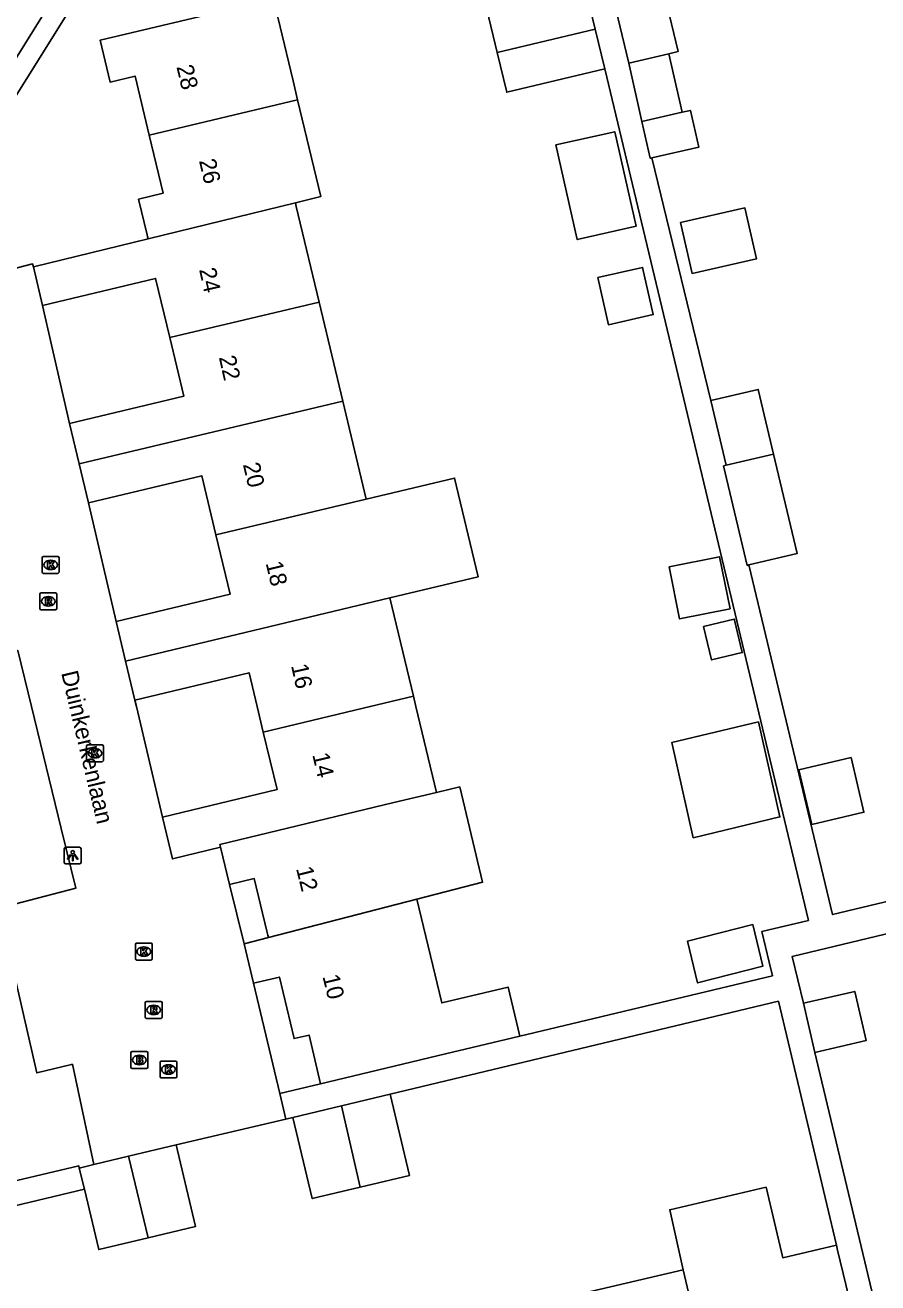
# Model space of a CAD drawing. Extents: x 158474 to 159560, y 388525 to 389605.
# Drawn here: x 159385.3 to 159435.9, y 388715.8 to 388790.4 of the extents above; entities that cross this region are included whole.
import ezdxf

# ---------------------------------------------------------------- set-up
doc = ezdxf.new("R2010")
doc.units = 0
for name, color, linetype in [('IMGEO_Brandkraan', 7, 'Continuous'), ('IMGEO_Kolk', 7, 'Continuous'), ('IMGEO_Lichtpunt', 7, 'Continuous'), ('IMGEO_Muur', 7, 'Continuous'), ('IMGEO_Openbare_ruimte_label', 7, 'Continuous'), ('IMGEO_Pand', 7, 'Continuous'), ('IMGEO_Pand_nummerreeks', 7, 'Continuous'), ('IMGEO_Rijbaan_lokaal_open', 7, 'Continuous'), ('IMGEO_Rioolput', 7, 'Continuous'), ('IMGEO_Voetpad_open', 7, 'Continuous')]:
    doc.layers.add(name, color=color, linetype=linetype)

msp = doc.modelspace()

# ---------------------------------------------------------------- linework, layer by layer
at = {"layer": 'IMGEO_Brandkraan'}
for p, q in [((159391.554, 388728.601), (159391.554, 388729.453)), ((159391.629, 388729.527), (159392.481, 388729.527)), ((159392.555, 388729.453), (159392.555, 388728.601)), ((159392.065, 388728.747), (159392.04, 388728.747)), ((159392.042, 388729.307), (159392.067, 388729.307)), ((159392.481, 388728.527), (159391.629, 388728.527))]:
    msp.add_line(p, q, dxfattribs=at)
for points in [[(159391.554, 388728.601), (159391.554, 388729.453)], [(159391.629, 388729.527), (159392.481, 388729.527)], [(159392.555, 388729.453), (159392.555, 388728.601)], [(159391.902, 388729.227), (159391.902, 388728.827), (159392.115, 388728.827)], [(159392.133, 388729.227), (159391.902, 388729.227)], [(159392.081, 388729.146), (159392.027, 388729.146), (159392.027, 388729.07)], [(159392.027, 388729.07), (159392.08, 388729.07)], [(159392.089, 388728.994), (159392.027, 388728.994), (159392.027, 388728.913)], [(159392.027, 388728.913), (159392.089, 388728.913)], [(159392.481, 388728.527), (159391.629, 388728.527)]]:
    msp.add_lwpolyline(points, dxfattribs=at)
for centre, radius, start, end in [((159391.631, 388729.451), 0.0765, 91.55205, 178.44795), ((159391.631, 388729.451), 0.0765, 91.55205, 178.44795), ((159392.479, 388729.451), 0.0765, 1.55205, 88.44795), ((159392.479, 388729.451), 0.0765, 1.55205, 88.44795), ((159392.082, 388729.108), 0.0379, 267.82845, 90.93552), ((159392.09, 388728.953), 0.0404, 269.87594, 90.50774), ((159392.121, 388729.078), 0.251, 268.66757, 293.53466), ((159392.137, 388729.082), 0.145, 59.4692, 91.53667), ((159392.162, 388729.129), 0.0922, 285.51372, 58.15012), ((159392.167, 388728.937), 0.105, 301.31148, 78.98903), ((159391.631, 388728.603), 0.0765, 181.55205, 268.44795), ((159391.631, 388728.603), 0.0765, 181.55205, 268.44795), ((159392.479, 388728.603), 0.0765, 271.55205, 358.44795), ((159392.479, 388728.603), 0.0765, 271.55205, 358.44795)]:
    msp.add_arc(centre, radius, start, end, dxfattribs=at)
for centre, major_axis, ratio, start_param, end_param in [((159392.041, 388729.027), (-0.387, 0.002), 0.722429, 4.712389, 7.853982), ((159392.066, 388729.027), (-0.39, 0.002), 0.717154, 1.570796, 4.712389)]:
    msp.add_ellipse(centre, major_axis=major_axis, ratio=ratio, start_param=start_param, end_param=end_param, dxfattribs=at)
at = {"layer": 'IMGEO_Kolk'}
for p, q in [((159386.289, 388757.982), (159386.289, 388758.834)), ((159386.364, 388758.908), (159387.216, 388758.908)), ((159386.777, 388758.688), (159386.802, 388758.688)), ((159387.29, 388758.834), (159387.29, 388757.982)), ((159387.216, 388757.908), (159386.364, 388757.908)), ((159386.8, 388758.128), (159386.775, 388758.128)), ((159388.919, 388746.805), (159388.919, 388747.657)), ((159388.994, 388747.731), (159389.846, 388747.731)), ((159389.407, 388747.511), (159389.432, 388747.511)), ((159389.92, 388747.657), (159389.92, 388746.805)), ((159389.846, 388746.731), (159388.994, 388746.731)), ((159389.43, 388746.951), (159389.405, 388746.951)), ((159391.819, 388735.034), (159391.819, 388735.886)), ((159391.894, 388735.96), (159392.746, 388735.96)), ((159392.307, 388735.74), (159392.332, 388735.74)), ((159392.82, 388735.886), (159392.82, 388735.034)), ((159392.746, 388734.96), (159391.894, 388734.96)), ((159392.33, 388735.18), (159392.305, 388735.18)), ((159393.281, 388728.037), (159393.281, 388728.889)), ((159393.356, 388728.963), (159394.208, 388728.963)), ((159393.769, 388728.743), (159393.794, 388728.743)), ((159394.282, 388728.889), (159394.282, 388728.037)), ((159394.208, 388727.963), (159393.356, 388727.963)), ((159393.792, 388728.183), (159393.767, 388728.183))]:
    msp.add_line(p, q, dxfattribs=at)
for points in [[(159386.289, 388757.982), (159386.289, 388758.834)], [(159386.364, 388758.908), (159387.216, 388758.908)], [(159386.61, 388758.608), (159386.733, 388758.608), (159386.733, 388758.457), (159386.863, 388758.608), (159387.027, 388758.608), (159386.881, 388758.457), (159387.034, 388758.208), (159386.882, 388758.208), (159386.797, 388758.372), (159386.733, 388758.305), (159386.733, 388758.208), (159386.61, 388758.208), (159386.61, 388758.608)], [(159387.29, 388758.834), (159387.29, 388757.982)], [(159387.216, 388757.908), (159386.364, 388757.908)], [(159388.919, 388746.805), (159388.919, 388747.657)], [(159388.994, 388747.731), (159389.846, 388747.731)], [(159389.24, 388747.431), (159389.363, 388747.431), (159389.363, 388747.28), (159389.493, 388747.431), (159389.657, 388747.431), (159389.511, 388747.28), (159389.664, 388747.031), (159389.512, 388747.031), (159389.427, 388747.195), (159389.363, 388747.128), (159389.363, 388747.031), (159389.24, 388747.031), (159389.24, 388747.431)], [(159389.92, 388747.657), (159389.92, 388746.805)], [(159389.846, 388746.731), (159388.994, 388746.731)], [(159391.819, 388735.034), (159391.819, 388735.886)], [(159391.894, 388735.96), (159392.746, 388735.96)], [(159392.14, 388735.66), (159392.263, 388735.66), (159392.263, 388735.509), (159392.393, 388735.66), (159392.557, 388735.66), (159392.411, 388735.509), (159392.564, 388735.26), (159392.412, 388735.26), (159392.327, 388735.424), (159392.263, 388735.357), (159392.263, 388735.26), (159392.14, 388735.26), (159392.14, 388735.66)], [(159392.82, 388735.886), (159392.82, 388735.034)], [(159392.746, 388734.96), (159391.894, 388734.96)], [(159393.281, 388728.037), (159393.281, 388728.889)], [(159393.356, 388728.963), (159394.208, 388728.963)], [(159393.602, 388728.663), (159393.725, 388728.663), (159393.725, 388728.512), (159393.855, 388728.663), (159394.019, 388728.663), (159393.873, 388728.512), (159394.026, 388728.263), (159393.874, 388728.263), (159393.789, 388728.427), (159393.725, 388728.36), (159393.725, 388728.263), (159393.602, 388728.263), (159393.602, 388728.663)], [(159394.282, 388728.889), (159394.282, 388728.037)], [(159394.208, 388727.963), (159393.356, 388727.963)]]:
    msp.add_lwpolyline(points, dxfattribs=at)
for centre, start, end in [((159386.366, 388758.832), 91.55205, 178.44795), ((159386.366, 388758.832), 91.55205, 178.44795), ((159387.214, 388758.832), 1.55205, 88.44795), ((159387.214, 388758.832), 1.55205, 88.44795), ((159386.366, 388757.984), 181.55205, 268.44795), ((159386.366, 388757.984), 181.55205, 268.44795), ((159387.214, 388757.984), 271.55205, 358.44795), ((159387.214, 388757.984), 271.55205, 358.44795), ((159388.996, 388747.655), 91.55205, 178.44795), ((159388.996, 388747.655), 91.55205, 178.44795), ((159389.844, 388747.655), 1.55205, 88.44795), ((159389.844, 388747.655), 1.55205, 88.44795), ((159388.996, 388746.807), 181.55205, 268.44795), ((159388.996, 388746.807), 181.55205, 268.44795), ((159389.844, 388746.807), 271.55205, 358.44795), ((159389.844, 388746.807), 271.55205, 358.44795), ((159391.896, 388735.884), 91.55205, 178.44795), ((159391.896, 388735.884), 91.55205, 178.44795), ((159392.744, 388735.884), 1.55205, 88.44795), ((159392.744, 388735.884), 1.55205, 88.44795), ((159391.896, 388735.036), 181.55205, 268.44795), ((159391.896, 388735.036), 181.55205, 268.44795), ((159392.744, 388735.036), 271.55205, 358.44795), ((159392.744, 388735.036), 271.55205, 358.44795), ((159393.358, 388728.887), 91.55205, 178.44795), ((159393.358, 388728.887), 91.55205, 178.44795), ((159394.206, 388728.887), 1.55205, 88.44795), ((159394.206, 388728.887), 1.55205, 88.44795), ((159393.358, 388728.039), 181.55205, 268.44795), ((159393.358, 388728.039), 181.55205, 268.44795), ((159394.206, 388728.039), 271.55205, 358.44795), ((159394.206, 388728.039), 271.55205, 358.44795)]:
    msp.add_arc(centre, 0.0765, start, end, dxfattribs=at)
for centre, major_axis, ratio, start_param, end_param in [((159386.776, 388758.408), (-0.387, 0.002), 0.722429, 4.712389, 7.853982), ((159386.801, 388758.408), (-0.39, 0.002), 0.717154, 1.570796, 4.712389), ((159389.406, 388747.231), (-0.387, 0.002), 0.722429, 4.712389, 7.853982), ((159389.431, 388747.231), (-0.39, 0.002), 0.717154, 1.570796, 4.712389), ((159392.306, 388735.46), (-0.387, 0.002), 0.722429, 4.712389, 7.853982), ((159392.331, 388735.46), (-0.39, 0.002), 0.717154, 1.570796, 4.712389), ((159393.768, 388728.463), (-0.387, 0.002), 0.722429, 4.712389, 7.853982), ((159393.793, 388728.463), (-0.39, 0.002), 0.717154, 1.570796, 4.712389)]:
    msp.add_ellipse(centre, major_axis=major_axis, ratio=ratio, start_param=start_param, end_param=end_param, dxfattribs=at)
at = {"layer": 'IMGEO_Lichtpunt'}
for p, q in [((159387.604, 388741.56), (159387.604, 388740.753)), ((159387.604, 388741.56), (159387.604, 388740.753)), ((159388.506, 388741.655), (159387.698, 388741.655)), ((159388.506, 388741.655), (159387.698, 388741.655)), ((159388.6, 388740.753), (159388.6, 388741.56)), ((159388.6, 388740.753), (159388.6, 388741.56)), ((159387.698, 388740.659), (159388.506, 388740.659)), ((159387.698, 388740.659), (159388.506, 388740.659))]:
    msp.add_line(p, q, dxfattribs=at)
for points in [[(159387.978, 388741.224), (159388.017, 388741.196), (159387.829, 388740.934), (159387.791, 388740.961), (159387.978, 388741.224)], [(159388.08, 388741.176), (159388.127, 388741.176), (159388.127, 388740.854), (159388.08, 388740.854), (159388.08, 388741.176)], [(159388.19, 388741.196), (159388.228, 388741.223), (159388.415, 388740.961), (159388.376, 388740.933), (159388.19, 388741.196)]]:
    msp.add_lwpolyline(points, dxfattribs=at)
msp.add_circle((159388.103, 388741.358), 0.0994, dxfattribs=at)
for centre, start, end in [((159387.698, 388741.56), 90, 180), ((159387.698, 388741.56), 90, 180), ((159388.506, 388741.56), 0, 90), ((159388.506, 388741.56), 0, 90), ((159387.698, 388740.753), 180, 270), ((159387.698, 388740.753), 180, 270), ((159388.506, 388740.753), 270, 0), ((159388.506, 388740.753), 270, 360)]:
    msp.add_arc(centre, 0.0946, start, end, dxfattribs=at)
at = {"layer": 'IMGEO_Muur'}
msp.add_lwpolyline([(159387.423, 388742.761), (159388.286, 388739.218), (159383.725, 388738.038), (159385.965, 388728.26)], dxfattribs=at)
at = {"layer": 'IMGEO_Pand'}
for points in [[(159423.461, 388788.75), (159424.026, 388788.885), (159422.862, 388793.751), (159419.933, 388793.05)], [(159419.933, 388793.05), (159421.097, 388788.185)], [(159413.28, 388788.827), (159412.672, 388791.371), (159418.487, 388792.761)], [(159418.487, 388792.761), (159419.097, 388790.21)], [(159392.638, 388783.919), (159391.801, 388787.419), (159390.318, 388787.064), (159389.724, 388789.548), (159400.007, 388792.007), (159401.17, 388787.145), (159401.441, 388786.012)], [(159413.28, 388788.827), (159419.097, 388790.21)], [(159419.097, 388790.21), (159419.661, 388787.851)], [(159419.661, 388787.851), (159413.846, 388786.461), (159413.28, 388788.827)], [(159423.461, 388788.75), (159421.097, 388788.185)], [(159424.25, 388785.271), (159423.461, 388788.75)], [(159421.097, 388788.185), (159421.863, 388784.731)], [(159392.638, 388783.919), (159401.441, 388786.012)], [(159401.441, 388786.012), (159402.814, 388780.269), (159401.309, 388779.901)], [(159422.462, 388782.565), (159425.243, 388783.195), (159424.747, 388785.384), (159424.25, 388785.271)], [(159424.25, 388785.271), (159421.863, 388784.731)], [(159421.863, 388784.731), (159422.359, 388782.542), (159422.462, 388782.565)], [(159392.57, 388777.764), (159392.537, 388777.902), (159392.513, 388778.004), (159392.008, 388780.114), (159393.464, 388780.462), (159392.638, 388783.919)], [(159416.765, 388783.33), (159420.253, 388784.12), (159421.524, 388778.511), (159418.036, 388777.721), (159416.765, 388783.33)], [(159401.309, 388779.901), (159392.57, 388777.764)], [(159401.309, 388779.901), (159401.364, 388779.671), (159401.48, 388779.185), (159402.719, 388774.005)], [(159424.158, 388778.727), (159424.842, 388775.707), (159428.659, 388776.571), (159427.975, 388779.591), (159424.158, 388778.727)], [(159385.766, 388776.1), (159392.57, 388777.764)], [(159385.766, 388776.1), (159386.315, 388773.807)], [(159419.25, 388775.463), (159419.885, 388772.659), (159422.541, 388773.261), (159421.906, 388776.065), (159419.25, 388775.463)], [(159386.315, 388773.807), (159393.021, 388775.411), (159393.859, 388771.909)], [(159393.859, 388771.909), (159402.719, 388774.005)], [(159402.719, 388774.005), (159404.122, 388768.136)], [(159393.859, 388771.909), (159394.693, 388768.421), (159387.918, 388766.801)], [(159429.681, 388764.989), (159428.769, 388768.826), (159425.962, 388768.159)], [(159388.49, 388764.41), (159404.122, 388768.136)], [(159404.122, 388768.136), (159405.516, 388762.308)], [(159425.962, 388768.159), (159426.874, 388764.322)], [(159387.918, 388766.801), (159388.49, 388764.41)], [(159429.681, 388764.989), (159426.874, 388764.322)], [(159428.218, 388758.404), (159431.085, 388759.086), (159429.681, 388764.989)], [(159388.49, 388764.41), (159389.044, 388762.095)], [(159426.874, 388764.322), (159426.714, 388764.284), (159428.118, 388758.38), (159428.218, 388758.404)], [(159389.044, 388762.095), (159395.756, 388763.7), (159396.595, 388760.189)], [(159406.918, 388756.445), (159412.154, 388757.693), (159410.756, 388763.557), (159405.516, 388762.308)], [(159405.516, 388762.308), (159396.595, 388760.189)], [(159396.595, 388760.189), (159397.437, 388756.667), (159390.671, 388755.049)], [(159423.489, 388758.294), (159424.107, 388755.208), (159427.098, 388755.807), (159426.48, 388758.893), (159423.489, 388758.294)], [(159391.231, 388752.705), (159406.918, 388756.445)], [(159406.918, 388756.445), (159408.313, 388750.609)], [(159390.671, 388755.049), (159391.231, 388752.705)], [(159425.529, 388754.761), (159426.002, 388752.77), (159427.822, 388753.203), (159427.364, 388755.129), (159427.348, 388755.194), (159425.529, 388754.761)], [(159391.231, 388752.705), (159391.785, 388750.39)], [(159391.785, 388750.39), (159398.563, 388752.01), (159399.044, 388750), (159399.405, 388748.489)], [(159399.405, 388748.489), (159405.755, 388750), (159408.313, 388750.609)], [(159408.313, 388750.609), (159408.459, 388750), (159409.677, 388744.904)], [(159428.783, 388749.088), (159423.652, 388747.87), (159424.909, 388742.216), (159430.059, 388743.454), (159428.783, 388749.088)], [(159399.405, 388748.489), (159400.222, 388745.072), (159393.425, 388743.447)], [(159431.174, 388746.243), (159434.273, 388746.974), (159435.039, 388743.728), (159431.94, 388742.997), (159431.174, 388746.243)], [(159408.525, 388738.57), (159412.42, 388739.578), (159411.062, 388745.236), (159409.677, 388744.904)], [(159409.677, 388744.904), (159407.156, 388744.299), (159396.833, 388741.82), (159396.875, 388741.647)], [(159393.425, 388743.447), (159394.019, 388740.964), (159396.875, 388741.647)], [(159396.875, 388741.647), (159397.403, 388739.444)], [(159397.403, 388739.444), (159398.869, 388739.795), (159399.617, 388736.666), (159399.672, 388736.434), (159399.707, 388736.287)], [(159399.707, 388736.287), (159408.525, 388738.57)], [(159408.525, 388738.57), (159409.997, 388732.413), (159413.931, 388733.354), (159414.628, 388730.439)], [(159428.447, 388737.066), (159424.577, 388736.079), (159425.171, 388733.602), (159429.041, 388734.588), (159428.447, 388737.066)], [(159398.272, 388735.915), (159399.707, 388736.287)], [(159398.272, 388735.915), (159398.83, 388733.577)], [(159402.811, 388727.613), (159402.12, 388730.504), (159401.235, 388730.293), (159400.362, 388733.944), (159398.83, 388733.577)], [(159432.128, 388729.477), (159435.162, 388730.175), (159434.491, 388733.097), (159431.457, 388732.399)], [(159431.457, 388732.399), (159432.128, 388729.477)], [(159414.628, 388730.439), (159409.795, 388729.283), (159407.674, 388728.776), (159402.811, 388727.613)], [(159404.044, 388726.31), (159406.926, 388726.999)], [(159406.926, 388726.999), (159408.079, 388722.178), (159405.163, 388721.481)], [(159401.154, 388725.619), (159404.044, 388726.31)], [(159405.163, 388721.481), (159404.044, 388726.31)], [(159405.163, 388721.481), (159402.307, 388720.798), (159401.154, 388725.619)], [(159391.407, 388723.308), (159394.237, 388723.984)], [(159394.237, 388723.984), (159395.393, 388719.148), (159392.568, 388718.472)], [(159389.359, 388722.818), (159388.491, 388722.61)], [(159391.407, 388723.308), (159389.359, 388722.818)], [(159392.568, 388718.472), (159391.407, 388723.308)], [(159388.792, 388721.352), (159388.491, 388722.61)], [(159388.792, 388721.352), (159389.648, 388717.774), (159392.568, 388718.472)], [(159424.318, 388716.568), (159423.521, 388720.136), (159429.239, 388721.477), (159430.222, 388717.29), (159433.412, 388718.04)], [(159433.412, 388718.04), (159433.481, 388717.747), (159433.96, 388715.708), (159435.103, 388710.84)], [(159418.48, 388715.197), (159424.318, 388716.568)], [(159426.388, 388707.732), (159424.318, 388716.568)]]:
    msp.add_lwpolyline(points, dxfattribs=at)
at = {"layer": 'IMGEO_Rijbaan_lokaal_open'}
for points in [[(159387.725, 388793.314), (159383.331, 388786.236)], [(159380.215, 388776.067), (159380.334, 388775.621), (159381.246, 388775.115), (159385.725, 388776.273), (159385.766, 388776.1)], [(159387.918, 388766.801), (159386.315, 388773.807)], [(159390.671, 388755.049), (159389.044, 388762.095)], [(159383.582, 388753.035), (159384.846, 388753.338), (159385.66, 388750), (159387.423, 388742.761), (159388.286, 388739.218), (159383.725, 388738.038), (159385.965, 388728.26), (159388.038, 388728.76), (159388.081, 388728.77), (159389.359, 388722.818)], [(159393.425, 388743.447), (159391.878, 388750), (159391.785, 388750.39)], [(159397.403, 388739.444), (159398.272, 388735.915)], [(159398.83, 388733.577), (159400.389, 388727.036)], [(159400.389, 388727.036), (159400.75, 388725.523)], [(159400.75, 388725.523), (159394.237, 388723.984)]]:
    msp.add_lwpolyline(points, dxfattribs=at)
at = {"layer": 'IMGEO_Rioolput'}
for p, q in [((159386.15, 388755.821), (159386.15, 388756.673)), ((159386.225, 388756.747), (159387.077, 388756.747)), ((159386.638, 388756.527), (159386.663, 388756.527)), ((159387.151, 388756.673), (159387.151, 388755.821)), ((159387.077, 388755.747), (159386.225, 388755.747)), ((159386.661, 388755.967), (159386.636, 388755.967)), ((159392.404, 388731.571), (159392.404, 388732.423)), ((159392.479, 388732.497), (159393.331, 388732.497)), ((159393.405, 388732.423), (159393.405, 388731.571)), ((159392.915, 388731.717), (159392.89, 388731.717)), ((159392.892, 388732.277), (159392.917, 388732.277)), ((159393.331, 388731.497), (159392.479, 388731.497))]:
    msp.add_line(p, q, dxfattribs=at)
for points in [[(159386.15, 388755.821), (159386.15, 388756.673)], [(159386.225, 388756.747), (159387.077, 388756.747)], [(159386.739, 388756.445), (159386.487, 388756.447), (159386.487, 388756.047)], [(159386.665, 388756.366), (159386.611, 388756.366), (159386.611, 388756.285)], [(159386.611, 388756.285), (159386.663, 388756.285)], [(159387.151, 388756.673), (159387.151, 388755.821)], [(159387.077, 388755.747), (159386.225, 388755.747)], [(159386.487, 388756.047), (159386.611, 388756.047), (159386.611, 388756.209), (159386.622, 388756.209)], [(159386.669, 388756.18), (159386.74, 388756.047), (159386.88, 388756.047), (159386.815, 388756.173)], [(159392.404, 388731.571), (159392.404, 388732.423)], [(159392.479, 388732.497), (159393.331, 388732.497)], [(159393.405, 388732.423), (159393.405, 388731.571)], [(159392.993, 388732.195), (159392.741, 388732.197), (159392.741, 388731.797)], [(159392.741, 388731.797), (159392.865, 388731.797), (159392.865, 388731.959), (159392.876, 388731.959)], [(159392.919, 388732.116), (159392.865, 388732.116), (159392.865, 388732.035)], [(159392.865, 388732.035), (159392.917, 388732.035)], [(159392.923, 388731.93), (159392.994, 388731.797), (159393.134, 388731.797), (159393.069, 388731.923)], [(159393.331, 388731.497), (159392.479, 388731.497)]]:
    msp.add_lwpolyline(points, dxfattribs=at)
for centre, radius, start, end in [((159386.227, 388756.671), 0.0765, 91.55205, 178.44795), ((159386.227, 388756.671), 0.0765, 91.55205, 178.44795), ((159386.647, 388756.474), 0.19, 274.7715, 282.96867), ((159386.671, 388756.27), 0.0964, 77.00612, 93.18647), ((159386.685, 388756.327), 0.0378, 276.66336, 79.67722), ((159386.738, 388756.335), 0.109, 350.36119, 89.41601), ((159386.736, 388756.335), 0.112, 277.58423, 350.98172), ((159387.075, 388756.671), 0.0765, 1.55205, 88.44795), ((159387.075, 388756.671), 0.0765, 1.55205, 88.44795), ((159386.227, 388755.823), 0.0765, 181.55205, 268.44795), ((159386.227, 388755.823), 0.0765, 181.55205, 268.44795), ((159386.621, 388756.156), 0.0533, 26.02933, 88.69889), ((159386.72, 388756.12), 0.108, 29.51342, 73.79051), ((159387.075, 388755.823), 0.0765, 271.55205, 358.44795), ((159387.075, 388755.823), 0.0765, 271.55205, 358.44795), ((159392.481, 388732.421), 0.0765, 91.55205, 178.44795), ((159392.481, 388732.421), 0.0765, 91.55205, 178.44795), ((159393.329, 388732.421), 0.0765, 1.55205, 88.44795), ((159393.329, 388732.421), 0.0765, 1.55205, 88.44795), ((159392.875, 388731.906), 0.0533, 26.02933, 88.69889), ((159392.901, 388732.224), 0.19, 274.7715, 282.96867), ((159392.925, 388732.02), 0.0964, 77.00612, 93.18647), ((159392.939, 388732.077), 0.0378, 276.66336, 79.67722), ((159392.992, 388732.085), 0.109, 350.36119, 89.41601), ((159392.99, 388732.085), 0.112, 277.58423, 350.98172), ((159392.974, 388731.87), 0.108, 29.51342, 73.79051), ((159392.481, 388731.573), 0.0765, 181.55205, 268.44795), ((159392.481, 388731.573), 0.0765, 181.55205, 268.44795), ((159393.329, 388731.573), 0.0765, 271.55205, 358.44795), ((159393.329, 388731.573), 0.0765, 271.55205, 358.44795)]:
    msp.add_arc(centre, radius, start, end, dxfattribs=at)
for centre, major_axis, ratio, start_param, end_param in [((159386.637, 388756.247), (-0.387, 0.002), 0.722429, 4.712389, 7.853982), ((159386.662, 388756.247), (-0.39, 0.002), 0.717154, 1.570796, 4.712389), ((159392.891, 388731.997), (-0.387, 0.002), 0.722429, 4.712389, 7.853982), ((159392.916, 388731.997), (-0.39, 0.002), 0.717154, 1.570796, 4.712389)]:
    msp.add_ellipse(centre, major_axis=major_axis, ratio=ratio, start_param=start_param, end_param=end_param, dxfattribs=at)
at = {"layer": 'IMGEO_Voetpad_open'}
for points in [[(159380.215, 388776.067), (159379.662, 388778.147), (159387.903, 388791.333)], [(159419.661, 388787.851), (159431.745, 388737.312), (159428.98, 388736.651), (159429.417, 388734.822), (159429.608, 388734.021), (159414.628, 388730.439)], [(159422.462, 388782.565), (159425.962, 388768.159)], [(159428.218, 388758.404), (159433.179, 388737.655), (159447.665, 388741.119)], [(159440.251, 388737.438), (159430.784, 388735.174), (159431.457, 388732.399)], [(159406.926, 388726.999), (159429.97, 388732.509), (159433.412, 388718.04)], [(159432.128, 388729.477), (159437.093, 388708.671)], [(159400.389, 388727.036), (159402.811, 388727.613)], [(159400.75, 388725.523), (159401.154, 388725.619)], [(159388.491, 388722.61), (159388.458, 388722.747), (159384.796, 388721.87)], [(159376.802, 388718.484), (159388.792, 388721.352)]]:
    msp.add_lwpolyline(points, dxfattribs=at)

# ---------------------------------------------------------------- texts
at = {"layer": 'IMGEO_Openbare_ruimte_label'}
msp.add_text('Duinkerkenlaan', height=1, rotation=283.35534, dxfattribs=at).set_placement((159387.412, 388752.003))
at = {"layer": 'IMGEO_Pand_nummerreeks'}
for s, rotation, p in [('28', 283.4437, (159394.249, 388787.976)), ('26', 283.44138, (159395.586, 388782.397)), ('24', 282.81113, (159395.593, 388775.937)), ('22', 282.81132, (159396.766, 388770.729)), ('20', 283.44241, (159398.192, 388764.369)), ('18', 283.44241, (159399.544, 388758.513)), ('16', 282.51381, (159401.051, 388752.433)), ('14', 283.44138, (159402.307, 388747.149)), ('12', 283.97996, (159401.344, 388740.39)), ('10', 283.97996, (159402.912, 388733.988))]:
    msp.add_text(s, height=1, rotation=rotation, dxfattribs=at).set_placement(p)

doc.saveas('drawing.dxf')
